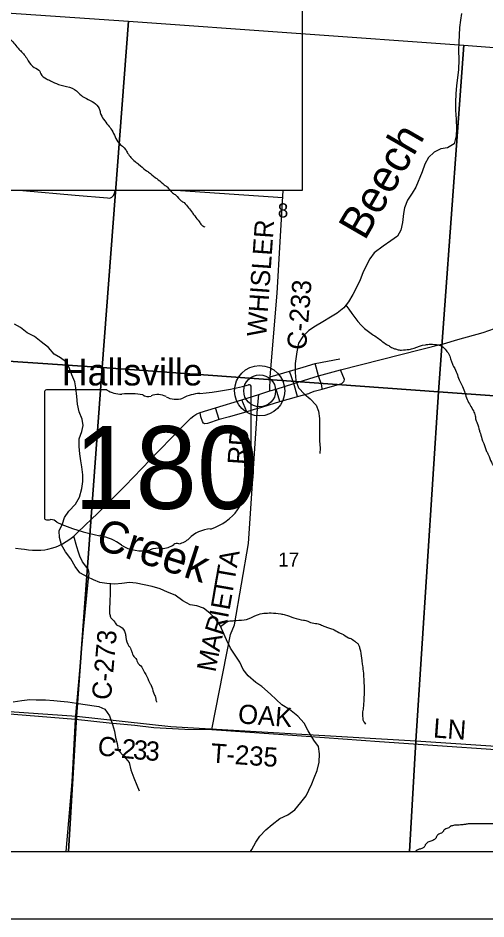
# Model space of a CAD drawing. Extents: x 0 to 42.5, y 0 to 22.
# Drawn here: x 5.494 to 6.186, y 14 to 15.332 of the extents above; entities that cross this region are included whole.
import ezdxf

# ---------------------------------------------------------------- set-up
doc = ezdxf.new("R2010")
doc.units = 0
for name, color, linetype in [('GM_X_County_Road', 7, 'Continuous'), ('GM_X_County_Road_Text', 7, 'Continuous'), ('GM_X_Interchange_Ramps', 7, 'Continuous'), ('GM_X_Minor_River', 7, 'Continuous'), ('GM_X_Minor_River_Text', 7, 'Continuous'), ('GM_X_Section', 7, 'Continuous'), ('GM_X_Section_Text', 7, 'Continuous'), ('GM_X_State_Location', 7, 'Continuous'), ('GM_X_State_Route', 7, 'Continuous'), ('GM_X_State_Shield', 7, 'Continuous'), ('GM_X_Township_Road', 7, 'Continuous'), ('GM_X_Township_Road_Text', 7, 'Continuous'), ('GM_X_Unincorporated', 7, 'Continuous'), ('GM_X_Unincorporated_Location', 7, 'Continuous'), ('GM_X_Unincorporated_Text', 7, 'Continuous'), ('SH_Cut_Line', 7, 'Continuous'), ('SH_Data', 7, 'Continuous'), ('SH_Text', 7, 'Continuous')]:
    doc.layers.add(name, color=color, linetype=linetype)

msp = doc.modelspace()

# ---------------------------------------------------------------- linework, layer by layer
at = {"layer": 'GM_X_County_Road'}
msp.add_line((5.85, 14.7755), (5.8667, 14.7808), dxfattribs=at)
for points in [[(5.8667, 14.7808), (5.867, 14.8016), (5.8773, 14.9253), (5.8863, 15.0772)], [(5.579, 14.2953), (5.629, 14.29), (5.6666, 14.2865), (5.6948, 14.2831), (5.7409, 14.2809), (5.7809, 14.2802), (5.8081, 14.4205), (5.8143, 14.4348), (5.835, 14.5551), (5.8483, 14.7548), (5.85, 14.7755)], [(5.579, 14.2953), (5.5906, 14.4282), (5.5984, 14.5036), (5.5991, 14.5109), (5.5982, 14.5161), (5.5956, 14.5199), (5.5895, 14.5284), (5.5856, 14.5363), (5.5835, 14.5424), (5.5808, 14.5501), (5.5763, 14.5659)], [(5.097, 14.2481), (5.0988, 14.2489), (5.1055, 14.328), (5.1087, 14.332), (5.1139, 14.3316), (5.3266, 14.3143), (5.4875, 14.303), (5.579, 14.2953)], [(5.5653, 14.1), (5.574, 14.2029), (5.579, 14.2953)]]:
    msp.add_lwpolyline(points, dxfattribs=at)
at = {"layer": 'GM_X_Interchange_Ramps'}
msp.add_lwpolyline([(5.162, 15.0772), (5.1421, 14.8012), (5.1259, 14.5975), (5.1076, 14.3533), (5.1054, 14.3283), (5.0987, 14.2492), (5.0849, 14.1), (8.0699, 14.1)], dxfattribs=at)
at = {"layer": 'GM_X_Minor_River'}
for points in [[(6.15, 15.3391), (6.1484, 15.3292), (6.1472, 15.3182), (6.1464, 15.3068), (6.1459, 15.2966), (6.1458, 15.2848), (6.1461, 15.2704), (6.1456, 15.2564), (6.1443, 15.2439), (6.1427, 15.2325), (6.1415, 15.22), (6.141, 15.2079), (6.1413, 15.1961), (6.1423, 15.1824), (6.1426, 15.1692), (6.1421, 15.1582), (6.139, 15.1464), (6.1295, 15.1404), (6.1196, 15.139), (6.1098, 15.1338), (6.101, 15.1263), (6.096, 15.1161), (6.0921, 15.1047), (6.0825, 15.0824), (6.0771, 15.0733), (6.0702, 15.0628), (6.0659, 15.0518), (6.0644, 15.0431), (6.0627, 15.0298), (6.0604, 15.0185), (6.0554, 15.0098), (6.0455, 15.0027)], [(6.0455, 15.0027), (6.0341, 14.9948), (6.0207, 14.985), (6.0146, 14.9764), (6.0092, 14.9658), (6.0042, 14.9556), (6, 14.9454), (5.9946, 14.934), (5.9892, 14.9235), (5.9827, 14.9125), (5.9758, 14.9038), (5.9663, 14.896), (5.956, 14.89), (5.9449, 14.8829), (5.9339, 14.8765), (5.9244, 14.8705), (5.9152, 14.8615), (5.9087, 14.8517), (5.9064, 14.8388), (5.9039, 14.8214), (5.9038, 14.8081), (5.9049, 14.7963), (5.909, 14.7853), (5.9176, 14.7761), (5.9262, 14.7692), (5.9349, 14.7596), (5.9386, 14.7509), (5.94, 14.7403), (5.9398, 14.7175), (5.9401, 14.7072), (5.9408, 14.6962), (5.9403, 14.6883)], [(5.5475, 14.8353), (5.5392, 14.8452), (5.5283, 14.8536), (5.5185, 14.8613), (5.5076, 14.8667), (5.4974, 14.8748), (5.4888, 14.8794)], [(5.8381, 14.1), (5.8398, 14.1026), (5.846, 14.1136), (5.8517, 14.1226), (5.8605, 14.1316), (5.8697, 14.1395), (5.8811, 14.1486), (5.8929, 14.1541), (5.9035, 14.1616), (5.9123, 14.1722), (5.9204, 14.182), (5.9242, 14.1907), (5.9284, 14.2001), (5.9323, 14.2088), (5.9366, 14.2198), (5.9393, 14.2319), (5.9398, 14.2441), (5.9384, 14.2551), (5.9316, 14.2646), (5.923, 14.278), (5.9171, 14.2894), (5.9081, 14.2997), (5.8956, 14.31), (5.8843, 14.3166), (5.8674, 14.3327), (5.8547, 14.3438), (5.846, 14.3499), (5.8343, 14.3595), (5.8269, 14.3687), (5.822, 14.3797), (5.8164, 14.3885), (5.8082, 14.4007), (5.8022, 14.4129), (5.797, 14.425), (5.7929, 14.4338), (5.7873, 14.4426), (5.7776, 14.4521), (5.7685, 14.4598), (5.7587, 14.4629), (5.7485, 14.4645), (5.7376, 14.4703), (5.7263, 14.4791), (5.715, 14.4834), (5.704, 14.488), (5.6923, 14.4915), (5.6806, 14.4943), (5.6685, 14.4967), (5.6591, 14.4975), (5.6477, 14.4961), (5.6371, 14.495), (5.6254, 14.4959), (5.6148, 14.4975), (5.6057, 14.5013), (5.597, 14.5056), (5.5854, 14.5118), (5.5786, 14.5213), (5.5723, 14.5324), (5.564, 14.543), (5.5581, 14.5533), (5.5551, 14.564), (5.5548, 14.5738), (5.5598, 14.5844), (5.5629, 14.5935), (5.5691, 14.6033), (5.579, 14.6135), (5.5851, 14.624), (5.5883, 14.6365), (5.5899, 14.6472), (5.5896, 14.6566), (5.5881, 14.6688), (5.5867, 14.6775), (5.5853, 14.6878), (5.5842, 14.6988), (5.5843, 14.7102), (5.5882, 14.7208), (5.5905, 14.7298), (5.5887, 14.7393), (5.5843, 14.75), (5.5821, 14.7614), (5.581, 14.7728), (5.5796, 14.7853), (5.5778, 14.7944), (5.5737, 14.8047), (5.57, 14.8142), (5.5663, 14.823), (5.5569, 14.8299), (5.5475, 14.8353)], [(5.4869, 14.321), (5.4994, 14.3232), (5.5112, 14.3246), (5.5206, 14.3241), (5.5346, 14.324), (5.5471, 14.3232), (5.557, 14.3223), (5.5675, 14.3211), (5.5804, 14.3191), (5.5899, 14.3175), (5.6137, 14.3143), (5.6223, 14.3104), (5.6291, 14.3005), (5.6339, 14.2875), (5.6365, 14.2777), (5.6383, 14.2685), (5.6405, 14.2594), (5.6423, 14.2495), (5.6509, 14.2404), (5.6584, 14.2316), (5.661, 14.2205), (5.6654, 14.2087), (5.6695, 14.1977), (5.6732, 14.1893)]]:
    msp.add_lwpolyline(points, dxfattribs=at)
for points in [[(5.1453, 15.8029), (5.1667, 15.772), (5.1755, 15.7626), (5.1789, 15.7567), (5.1905, 15.7437), (5.1978, 15.7392), (5.2095, 15.7302), (5.2163, 15.7271), (5.2254, 15.7188), (5.2301, 15.715), (5.2365, 15.7043), (5.24, 15.7001), (5.2452, 15.687), (5.2484, 15.6812), (5.254, 15.6658), (5.2573, 15.6601), (5.2638, 15.6485), (5.2707, 15.632), (5.2716, 15.6257), (5.2783, 15.6061), (5.282, 15.5981), (5.29, 15.5767), (5.2976, 15.5631), (5.3004, 15.5538), (5.3102, 15.5302), (5.3171, 15.5201), (5.3294, 15.4927), (5.3382, 15.4824), (5.3537, 15.4565), (5.3634, 15.4467), (5.3793, 15.4213), (5.3889, 15.4119), (5.4042, 15.3892), (5.413, 15.3808), (5.4272, 15.3603), (5.4424, 15.3438), (5.4504, 15.3337), (5.4664, 15.3182), (5.474, 15.309), (5.4877, 15.2954), (5.4939, 15.2879), (5.5044, 15.2764), (5.5091, 15.269), (5.518, 15.2592), (5.5261, 15.2536), (5.5276, 15.25), (5.536, 15.2423), (5.5421, 15.2396), (5.5537, 15.2341), (5.5616, 15.2321), (5.5777, 15.2268), (5.5878, 15.2176), (5.5951, 15.2133), (5.6139, 15.1987), (5.6157, 15.1924), (5.6273, 15.1739), (5.6327, 15.1665), (5.6434, 15.1472), (5.6529, 15.138), (5.6561, 15.1327), (5.667, 15.1204), (5.6724, 15.1162), (5.6825, 15.1075), (5.6872, 15.1044), (5.697, 15.0964), (5.7015, 15.0933), (5.7103, 15.0856), (5.7146, 15.0825), (5.7225, 15.0739), (5.7276, 15.0702), (5.7353, 15.0622), (5.7396, 15.0593), (5.746, 15.0518), (5.7519, 15.0445), (5.7553, 15.0396), (5.7619, 15.0315), (5.7652, 15.0266), (5.7703, 15.0237)], [(5.979, 14.9079), (6.0182, 14.8644), (6.0255, 14.8599), (6.039, 14.8497), (6.0435, 14.8472), (6.0497, 14.8437), (6.0524, 14.8429), (6.0576, 14.8415), (6.0614, 14.8414), (6.0726, 14.8424), (6.0798, 14.8442), (6.0966, 14.8493), (6.1043, 14.8499), (6.1157, 14.849), (6.1202, 14.8476), (6.1275, 14.8405), (6.1309, 14.8361), (6.1366, 14.8205), (6.1401, 14.8139), (6.1476, 14.7952), (6.1515, 14.7874), (6.1585, 14.7682), (6.1676, 14.7515), (6.1704, 14.744), (6.1711, 14.738), (6.1734, 14.7334), (6.1765, 14.7222), (6.178, 14.718), (6.1811, 14.7072), (6.183, 14.703), (6.1872, 14.6914), (6.1897, 14.6869), (6.1943, 14.6753), (6.1969, 14.6707), (6.2017, 14.6593), (6.2055, 14.6532), (6.2066, 14.649), (6.212, 14.6374), (6.2125, 14.6334), (6.2166, 14.622), (6.2188, 14.6171), (6.224, 14.6034), (6.2276, 14.5984), (6.2356, 14.5881), (6.2405, 14.5852), (6.2505, 14.5796), (6.2563, 14.5778), (6.2702, 14.5738), (6.2785, 14.5727), (6.2976, 14.5721), (6.3142, 14.5711), (6.3193, 14.5703), (6.3351, 14.5657), (6.3423, 14.5637), (6.3568, 14.5567), (6.3631, 14.5532), (6.3746, 14.5434), (6.39, 14.5311), (6.3965, 14.5246), (6.3984, 14.5189), (6.4078, 14.5119), (6.4108, 14.507), (6.4218, 14.4945), (6.4273, 14.4895), (6.4372, 14.4758), (6.4415, 14.4715), (6.449, 14.4614), (6.4521, 14.4576), (6.4579, 14.4484), (6.462, 14.4429), (6.4633, 14.4389), (6.4678, 14.4277), (6.47, 14.4229), (6.4748, 14.4074), (6.477, 14.4007), (6.4816, 14.3834), (6.4841, 14.3772), (6.4889, 14.3618), (6.4909, 14.3561), (6.494, 14.3422), (6.4964, 14.3346), (6.4971, 14.3299), (6.4995, 14.3183), (6.5008, 14.3147), (6.5028, 14.3058), (6.5047, 14.3016), (6.5052, 14.2988), (6.5076, 14.2919), (6.5093, 14.2893), (6.514, 14.2798), (6.519, 14.2736), (6.5209, 14.2698), (6.5297, 14.2597), (6.5417, 14.2537), (6.5434, 14.2512), (6.5477, 14.2492), (6.5556, 14.2451)], [(5.6305, 14.4955), (5.6301, 14.4889), (5.6303, 14.4827), (5.6301, 14.4774), (5.6294, 14.4619), (5.6293, 14.456), (5.6297, 14.4502), (5.6304, 14.4477), (5.6312, 14.4454), (5.6373, 14.4391), (5.6385, 14.4366), (5.6452, 14.4324), (5.6525, 14.4226), (5.6534, 14.4169), (5.6581, 14.4036), (5.6605, 14.4004), (5.6616, 14.3966), (5.6623, 14.3951), (5.6651, 14.3882), (5.6692, 14.3838), (5.6705, 14.38), (5.6771, 14.3724), (5.681, 14.3644), (5.6832, 14.3613), (5.6884, 14.3497), (5.6909, 14.3455), (5.6942, 14.3349), (5.6966, 14.3297), (5.6975, 14.3271), (5.6977, 14.3248), (5.6985, 14.3227), (5.699, 14.3204)], [(5.7936, 14.4323), (5.8095, 14.441), (5.811, 14.441), (5.8167, 14.4415), (5.8322, 14.443), (5.8469, 14.4494), (5.8577, 14.452), (5.8683, 14.4525), (5.8826, 14.4511), (5.8892, 14.4499), (5.9022, 14.4452), (5.9163, 14.4419), (5.9229, 14.4403), (5.9246, 14.4394), (5.9341, 14.4372), (5.9414, 14.4354), (5.9478, 14.4324), (5.9531, 14.4305), (5.9595, 14.4287), (5.9685, 14.4238), (5.973, 14.4219), (5.9828, 14.416), (5.9873, 14.4141), (5.9939, 14.4095), (5.9973, 14.4064), (5.9989, 14.4022), (5.9997, 14.3994), (6.0006, 14.3963), (6.0024, 14.3821), (6.0035, 14.3749), (6.0056, 14.3522), (6.0056, 14.3248), (6.005, 14.3172), (6.0041, 14.3082), (6.0035, 14.3042), (6.0039, 14.2976), (6.0042, 14.2946), (6.0061, 14.2909), (6.008, 14.2879)]]:
    msp.add_spline(points, degree=3, dxfattribs=at)
msp.add_open_spline([(6.3259, 14.1), (6.3257, 14.1002), (6.3255, 14.1005), (6.3253, 14.1008), (6.3243, 14.102), (6.3245, 14.1041), (6.3232, 14.1051), (6.3179, 14.1097), (6.3111, 14.1123), (6.3056, 14.1165), (6.2994, 14.1213), (6.2933, 14.1264), (6.2878, 14.1319), (6.2868, 14.1329), (6.2872, 14.1351), (6.2859, 14.1357), (6.281, 14.138), (6.276, 14.1401), (6.271, 14.1424), (6.2705, 14.1426), (6.2699, 14.1429), (6.2693, 14.1431), (6.2677, 14.1439), (6.2656, 14.1438), (6.2639, 14.1432), (6.2631, 14.143), (6.2624, 14.1425), (6.2616, 14.1423), (6.2596, 14.1417), (6.2576, 14.141), (6.2555, 14.1405), (6.2528, 14.1398), (6.2501, 14.1392), (6.2474, 14.1387), (6.2446, 14.1382), (6.2417, 14.138), (6.2389, 14.1383), (6.2383, 14.1383), (6.2378, 14.1386), (6.2372, 14.1387), (6.2304, 14.1391), (6.2236, 14.1393), (6.2168, 14.1397), (6.2157, 14.1398), (6.2146, 14.1399), (6.2134, 14.14), (6.2049, 14.1405), (6.1965, 14.141), (6.188, 14.1409), (6.1868, 14.1409), (6.1857, 14.1408), (6.1846, 14.1407), (6.176, 14.1405), (6.1674, 14.1409), (6.1589, 14.1404), (6.1578, 14.1403), (6.1567, 14.14), (6.1557, 14.1398), (6.1486, 14.1388), (6.1414, 14.1391), (6.1343, 14.1375), (6.1335, 14.1373), (6.1331, 14.1363), (6.1324, 14.1358), (6.1299, 14.1341), (6.1265, 14.1335), (6.1241, 14.1316), (6.1235, 14.1311), (6.1236, 14.1301), (6.1231, 14.1295), (6.1206, 14.1268), (6.1161, 14.1257), (6.1137, 14.1229), (6.1129, 14.122), (6.1129, 14.1207), (6.1121, 14.1198), (6.1083, 14.1156), (6.1011, 14.1147), (6.0971, 14.1106), (6.0962, 14.1096), (6.0961, 14.1077), (6.095, 14.1067), (6.0918, 14.1035), (6.0858, 14.1033), (6.0825, 14.1002), (6.0825, 14.1002), (6.0824, 14.1001), (6.0824, 14.1)], degree=3, dxfattribs=at)
at = {"layer": 'GM_X_Section'}
for points in [[(5.188, 15.3601), (5.6573, 15.3278), (5.6186, 14.8156), (5.149, 14.8472), (5.1833, 15.3031)], [(5.6573, 15.3278), (6.1534, 15.2921), (6.116, 14.7797), (5.6186, 14.8156)], [(6.1534, 15.2921), (6.6483, 15.2542), (6.6121, 14.7442), (6.116, 14.7797)], [(5.6186, 14.8156), (5.5806, 14.2995), (5.1051, 14.3325), (5.1432, 14.7839), (5.1456, 14.8014), (5.149, 14.8472)], [(6.116, 14.7797), (6.0824, 14.2629), (5.7198, 14.2842), (5.5806, 14.2995), (5.6186, 14.8156)], [(6.6121, 14.7442), (6.5774, 14.2301), (6.0824, 14.2629), (6.116, 14.7797)]]:
    msp.add_lwpolyline(points, close=True, dxfattribs=at)
at = {"layer": 'GM_X_State_Route'}
msp.add_line((5.85, 14.7755), (5.8667, 14.7808), dxfattribs=at)
for points in [[(6.1446, 14.8567), (6.1822, 14.8675), (6.1988, 14.8734)], [(6.1205, 14.8499), (6.1234, 14.8507), (6.1446, 14.8567)], [(5.8667, 14.7808), (5.8759, 14.7833), (5.9019, 14.7917), (5.9387, 14.8031), (5.9709, 14.8121), (6.1205, 14.8499)], [(5.6235, 14.6116), (5.6526, 14.6407), (5.7018, 14.692), (5.7441, 14.7353), (5.7495, 14.7406), (5.7541, 14.7441), (5.7587, 14.7468), (5.7633, 14.7489), (5.7863, 14.7561), (5.8249, 14.7676), (5.85, 14.7755)], [(5.6017, 14.5903), (5.6125, 14.6006), (5.6235, 14.6116)], [(5.4901, 14.5484), (5.4985, 14.5473), (5.5034, 14.5468), (5.5096, 14.5459), (5.5155, 14.5453), (5.5217, 14.5452), (5.5277, 14.5454), (5.5334, 14.5459), (5.5382, 14.5469), (5.5452, 14.5487), (5.5502, 14.5502), (5.5539, 14.5518), (5.5598, 14.5549), (5.5653, 14.5581), (5.5707, 14.5616), (5.5763, 14.5659), (5.5806, 14.5702), (5.5943, 14.5832), (5.6017, 14.5903)]]:
    msp.add_lwpolyline(points, dxfattribs=at)
at = {"layer": 'GM_X_State_Shield'}
for p, q in [((5.533, 14.7791), (5.533, 14.5934)), ((5.6256, 14.7823), (5.5361, 14.7823)), ((5.8389, 14.6897), (5.8389, 14.7869)), ((5.8388, 14.6898), (5.8389, 14.6897))]:
    msp.add_line(p, q, dxfattribs=at)
for centre, major_axis, start_param, end_param in [((5.7299, 15.0354), (0.3243, 0), 4.814394, 5.042369), ((5.8355, 14.7873), (0.0034, 0), 6.141152, 7.989035), ((5.5366, 14.7795), (0.00354, 0), 1.712693, 3.28349), ((5.6469, 14.8038), (0.0344, 0), 4.042523, 4.731795), ((5.6583, 14.678), (0.1234, 0), 1.404758, 1.657858), ((5.7009, 14.759), (0.0206, 0), 0.950623, 2.079405), ((5.7713, 14.7256), (0.0652, 0), 1.699011, 2.107814), ((5.6863, 14.7804), (0.00991, 0), 3.836095, 5.185415), ((5.7275, 14.7884), (0.0248, 0), 4.081561, 5.145723), ((5.8381, 14.6826), (0.00527, 0), 1.883978, 3.671073), ((5.8352, 14.6894), (0.00364, 0), 5.05454, 6.418171), ((5.8046, 14.6703), (0.0316, 0), 5.934695, 6.695948), ((5.8511, 14.6491), (0.023, 0), 2.387724, 3.262537), ((5.7481, 14.6367), (0.0811, 0), 5.101752, 6.440018), ((5.5366, 14.593), (0.00357, 0), 3.00124, 4.508301), ((5.5371, 14.612), (0.0273, 0), 4.665946, 4.897461), ((5.5427, 14.5827), (0.00984, 0), 0.519207, 1.627899), ((5.6669, 14.7495), (0.2342, 0), 4.195997, 4.488961), ((5.7823, 14.5413), (0.0444, 0), 1.647645, 2.488434), ((5.5971, 14.51), (0.0733, 0), 0.823519, 1.323587), ((5.726, 14.5754), (0.0262, 0), 4.937069, 5.64225), ((5.6763, 14.5817), (0.0465, 0), 4.026481, 4.996735), ((5.7066, 14.5678), (0.0248, 0), 4.691044, 5.507374), ((5.729, 14.5499), (0.00698, 0), 1.147584, 2.315152), ((5.7032, 14.5176), (0.0382, 0), 1.495662, 1.94098)]:
    msp.add_ellipse(centre, major_axis=major_axis, ratio=0.8, start_param=start_param, end_param=end_param, dxfattribs=at)
at = {"layer": 'GM_X_Township_Road'}
for p, q in [((5.7343, 15.0772), (5.8857, 15.067)), ((5.9387, 14.8031), (5.9337, 14.8213)), ((5.9019, 14.7917), (5.8956, 14.8102)), ((5.9075, 14.7726), (5.9019, 14.7917)), ((5.8811, 14.7651), (5.8759, 14.7833)), ((5.8323, 14.7502), (5.8249, 14.7676)), ((5.7915, 14.7384), (5.7863, 14.7561))]:
    msp.add_line(p, q, dxfattribs=at)
for points in [[(5.5009, 15.0772), (5.5785, 15.0703), (5.6265, 15.0663), (5.6299, 15.066), (5.6327, 15.0673), (5.6352, 15.0698), (5.6367, 15.0734), (5.6377, 15.0772)], [(5.867, 14.8016), (5.8956, 14.8102), (5.9158, 14.8161), (5.9337, 14.8213), (5.97, 14.8285)], [(5.906, 14.7722), (5.9075, 14.7726), (5.9242, 14.7771), (5.9263, 14.7781), (5.9321, 14.7803), (5.9381, 14.7818), (5.9439, 14.7834), (5.9434, 14.7888), (5.9387, 14.8031)], [(5.9439, 14.7834), (5.9731, 14.792), (5.975, 14.7937), (5.9761, 14.7948), (5.9763, 14.7959), (5.977, 14.7979), (5.9709, 14.8121)], [(5.8483, 14.7548), (5.8811, 14.7651), (5.906, 14.7722)], [(5.8483, 14.7548), (5.8323, 14.7502), (5.8066, 14.7425), (5.7915, 14.7384), (5.7744, 14.7329), (5.7704, 14.7322), (5.7683, 14.7332), (5.767, 14.7359), (5.7646, 14.7425), (5.7633, 14.7489)], [(5.7809, 14.2802), (5.8931, 14.2722), (6.0289, 14.2626), (6.2867, 14.2445)]]:
    msp.add_lwpolyline(points, dxfattribs=at)
at = {"layer": 'GM_X_Unincorporated'}
for points in [[(5.0862, 14.1), (5.5684, 14.1), (5.5806, 14.2995), (5.1051, 14.3325), (5.1039, 14.3089)], [(5.5684, 14.1), (6.0732, 14.1), (6.0824, 14.2629), (5.7198, 14.2842), (5.5806, 14.2995)], [(6.0732, 14.1), (6.5701, 14.1), (6.5774, 14.2301), (6.0824, 14.2629)]]:
    msp.add_lwpolyline(points, close=True, dxfattribs=at)
for radius in [0.0372, 0.0236]:
    msp.add_circle((5.8514, 14.7811), radius, dxfattribs=at)
at = {"layer": 'GM_X_Unincorporated_Location'}
msp.add_line((5.8514, 14.7811), (5.8514, 14.7811), dxfattribs=at)
at = {"layer": 'SH_Cut_Line'}
msp.add_lwpolyline([(2.1, 14.1), (8.0699, 14.1)], dxfattribs=at)
at = {"layer": 'SH_Data'}
for p, q in [((2.1, 14.1), (8.9, 14.1)), ((2, 14), (9, 14))]:
    msp.add_line(p, q, dxfattribs=at)
at = {"layer": 'SH_Text'}
msp.add_lwpolyline([(4.2087, 15.5307), (5.9141, 15.5307), (5.9141, 15.0772), (4.2087, 15.0772)], close=True, dxfattribs=at)

# ---------------------------------------------------------------- texts
at = {"layer": 'GM_X_County_Road_Text'}
for s, height, rotation, p in [('WHISLER', 0.02841, 86.0255, (5.861, 14.8605)), ('C-233', 0.02841, 85.3277, (5.92, 14.8408)), ('RD', 0.02841, 86.0533, (5.8321, 14.671)), ('A', 0.0284, 80.1373, (5.8177, 14.5185)), ('T', 0.0284, 80.129, (5.8141, 14.4975)), ('T', 0.0284, 80.1357, (5.8104, 14.4766)), ('E', 0.0284, 80.0425, (5.8068, 14.4556)), ('R', 0.0284, 72.5919, (5.7967, 14.418)), ('I', 0.0284, 79.295, (5.8045, 14.4437)), ('C-273', 0.02841, 85.0526, (5.6313, 14.3231)), ('A', 0.0284, 78.4993, (5.7919, 14.3942)), ('M', 0.0284, 79.0886, (5.786, 14.364)), ('C', 0.0284, 353.0831, (5.6105, 14.2426)), ('2', 0.0284, 354.1822, (5.6458, 14.2385)), ('3', 0.0284, 354.3132, (5.6633, 14.2368)), ('3', 0.0284, 355.7152, (5.6815, 14.235)), ('-', 0.0284, 354.0688, (5.6342, 14.2398))]:
    msp.add_text(s, height=height, rotation=rotation, dxfattribs=at).set_placement(p)
at = {"layer": 'GM_X_Minor_River_Text'}
for s, rotation, p in [('Beech', 60.001, (6.0069, 15.002)), ('Creek', 342.0002, (5.6064, 14.5489))]:
    msp.add_text(s, height=0.04735, rotation=rotation, dxfattribs=at).set_placement(p)
at = {"layer": 'GM_X_Section_Text'}
for s, height, p in [('8', 0.0209, (5.8783, 15.0374)), ('17', 0.02093, (5.8788, 14.521))]:
    msp.add_text(s, height=height, rotation=0, dxfattribs=at).set_placement(p)
at = {"layer": 'GM_X_State_Location'}
for s in ['s', 'r']:
    msp.add_text(s, height=0.0000947, dxfattribs=at).set_placement((5.7026, 14.6977))
msp.add_text('180', height=0.0000947, rotation=0, dxfattribs=at).set_placement((5.6692, 14.6908))
at = {"layer": 'GM_X_State_Shield'}
msp.add_text('180', height=0.12233, dxfattribs=at).set_placement((5.5766, 14.6065))
at = {"layer": 'GM_X_Township_Road_Text'}
for s, rotation, p in [('OAK', 355.869, (5.8187, 14.2894)), ('LN', 355.876, (6.1075, 14.2685)), ('T-235', 356.0742, (5.7783, 14.2315))]:
    msp.add_text(s, height=0.02841, rotation=rotation, dxfattribs=at).set_placement(p)
at = {"layer": 'GM_X_Unincorporated_Text'}
msp.add_text('Hallsville', height=0.03949, rotation=0, dxfattribs=at).set_placement((5.5588, 14.789))

doc.saveas('drawing.dxf')
